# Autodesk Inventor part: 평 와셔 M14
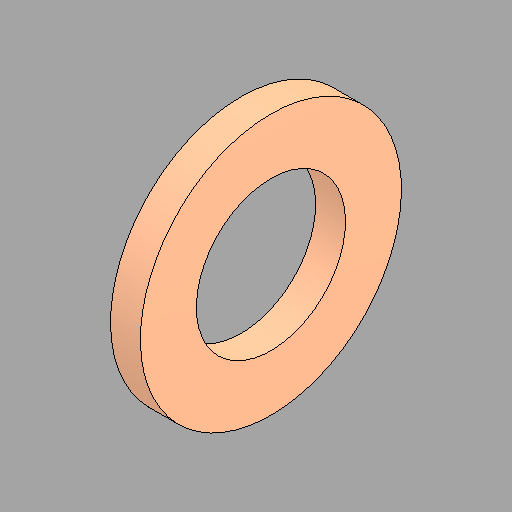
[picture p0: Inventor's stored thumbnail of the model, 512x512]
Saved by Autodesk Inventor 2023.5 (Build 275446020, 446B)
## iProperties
Created: 2025-07
Part Number: 평 와셔 M14
Material: 강철, 연강
Description: 평면 와셔
Document SubType Name: Modeling
Designer: 1강의실14
Density: 7.85 g/cm^3
Appearance: 기본값
Author: jhkim
Sending System: Autodesk Inventor 2026
Preprocessor: ST-DEVELOPER v20.1
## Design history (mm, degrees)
feature "Solid1"
node "솔리드1"
